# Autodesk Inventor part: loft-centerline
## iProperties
Shininess: 77.0
Angle Display Precision: 2
Document Length Units: 11269
Document Angle Units: 11279
Document Time Units: 11290
Document Mass Units: 11283
Document Length Units Precision: 3
Document Angle Units Precision: 2
Created: 2001-12
Part Number: loft-centerline
Document SubType Name: Modeling
Designer: CADSoft
Density: 1 g/cm^3
Density: 0.0
Volumn: 0.0
Area: 0.0
PropertySet Name: Model Information
Control State: 0
Master: False
Checked Out: False
Author: CADSoft
